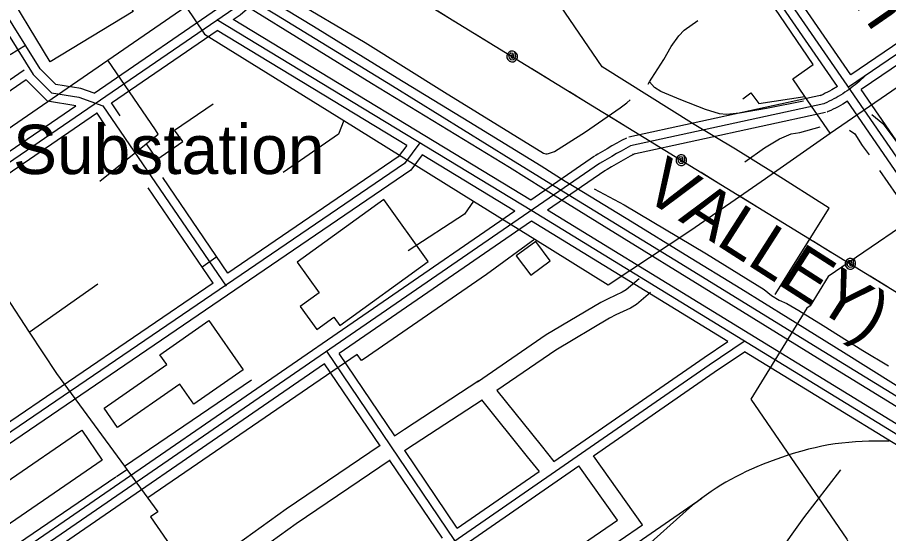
# Model space of a CAD drawing. Extents: x 3355724 to 3393621, y 594744 to 620174.
# Drawn here: x 3388659 to 3390126, y 612756 to 613624 of the extents above; entities that cross this region are included whole.
import ezdxf

# ---------------------------------------------------------------- set-up
doc = ezdxf.new("R2010")
doc.units = 0
for name, color, linetype in [('V-BLDG-OTLN', 7, 'Continuous'), ('V-RAIL-IDEN', 7, 'Continuous'), ('V-RAIL-TRAK', 7, 'Continuous'), ('V-ROAD-CNTR', 7, 'Continuous'), ('V-SITE-OTLN', 7, 'Continuous'), ('V-SITE-OTLN-IDEN', 7, 'Continuous'), ('V-TOPO-SHOR', 7, 'Continuous'), ('V-UTIL-LINE', 7, 'Continuous')]:
    doc.layers.add(name, color=color, linetype=linetype)

msp = doc.modelspace()

# ---------------------------------------------------------------- linework, layer by layer
at = {"layer": 'V-BLDG-OTLN'}
for points in [[(3389276.3, 613317.6), (3389130.3, 613212.5), (3389167.5, 613160.8), (3389135.6, 613137.8), (3389163.5, 613099), (3389192.3, 613119.7), (3389202.1, 613106), (3389351.3, 613213.3)], [(3389499.5, 613223.1), (3389523.8, 613190.3), (3389556.5, 613214.5), (3389532.3, 613247.3)], [(3388805.5, 612966.6), (3388910.8, 613039.9), (3388899.2, 613056.6), (3388982, 613114.2), (3389039.7, 613031.1), (3388956.3, 612973.1), (3388932.8, 613006.9), (3388828.1, 612934.1)], [(3388802, 612879.2), (3388593.4, 612736.1), (3388553.1, 612794.8), (3388634.4, 612850.6), (3388640.2, 612842), (3388767.7, 612929.4)]]:
    msp.add_lwpolyline(points, close=True, dxfattribs=at)
at = {"layer": 'V-RAIL-TRAK'}
for points in [[(3386835.4, 615018.6), (3387087.4, 614863.9), (3387313.5, 614724.5), (3387544.4, 614583), (3387825.6, 614410.3), (3388103.4, 614239), (3388374.3, 614072.6), (3388614, 613924.9), (3388857.9, 613775.8), (3389039.2, 613663.6), (3389053.7, 613654.6), (3389095.5, 613628.7), (3389291.1, 613509.4), (3389490.1, 613386), (3389587.1, 613326.5), (3389784.2, 613205.7), (3390000.1, 613072.5), (3390330.9, 612870), (3390414.6, 612817.9), (3390427.8, 612809.7), (3390622.7, 612689.7), (3390866.5, 612539.9), (3391139.5, 612371.4), (3391416.1, 612201.7)], [(3390974.6, 612456.2), (3390930.5, 612483.4), (3390784.4, 612573.4), (3390580, 612698.3), (3390429.2, 612790.4), (3390418.4, 612797), (3390349.8, 612839.6), (3390252.6, 612899.9), (3390033.2, 613034.5), (3389842.4, 613152.4), (3389647.5, 613272.3), (3389573.9, 613318.1), (3389487.9, 613371.5), (3389255.7, 613513), (3389041.3, 613645.3), (3389025.5, 613655.1), (3389018.6, 613659.3), (3388791.8, 613798.7), (3388745.6, 613827.1), (3388519.5, 613965.9)], [(3390176.9, 612981.4), (3390050.6, 613060.4), (3389957.5, 613118), (3389877.4, 613167.2), (3389783.7, 613224.8), (3389694.7, 613279.6), (3389599.6, 613337.6), (3389596.9, 613339.2), (3389582, 613348.3), (3389541.2, 613373.9), (3389419.7, 613448.8), (3389298.8, 613522.3), (3389158.2, 613609), (3389067.1, 613664.5)], [(3390127.6, 612911.2), (3390116.2, 612911.3), (3390104.8, 612911.2), (3390093.4, 612910.9), (3390082, 612910.5), (3390070.7, 612909.8), (3390059.3, 612908.9), (3390048, 612907.8), (3390036.6, 612906.5), (3390025.3, 612905), (3390014.1, 612902.7), (3390002.9, 612900.1), (3389991.7, 612897.4), (3389980.6, 612894.4), (3389969.5, 612891.2), (3389958.5, 612887.8), (3389947.6, 612884.2), (3389936.7, 612880.4), (3389925.9, 612876.4), (3389915.2, 612872.2), (3389904.6, 612867.9), (3389895.6, 612864), (3389886.8, 612859.9), (3389878.1, 612855.7), (3389869.4, 612851.3), (3389860.9, 612846.6), (3389852.4, 612841.8), (3389844.1, 612836.8), (3389835.9, 612831.7), (3389827.7, 612826.3), (3389819.8, 612820.8), (3389811.9, 612815.1), (3389804.1, 612809.2), (3389796.5, 612803.2), (3389704.7, 612721.2)], [(3389488, 612592.6), (3389696, 612735), (3389811.9, 612815.1)]]:
    msp.add_lwpolyline(points, dxfattribs=at)
at = {"layer": 'V-ROAD-CNTR'}
for p, q in [((3388647.3, 613561.9), (3388672.8, 613577.8)), ((3388970.4, 613204.7), (3388995.2, 613221.7))]:
    msp.add_line(p, q, dxfattribs=at)
for points in [[(3390234.3, 613253.1), (3389505.6, 614309.5)], [(3390063.1, 613527.6), (3389526.4, 614305.7)], [(3390040.3, 613507.8), (3389501.8, 614288.5)], [(3390888.5, 614071.8), (3390059.2, 613506.8)], [(3388788.5, 613496.8), (3388766.4, 613504.7), (3388724.2, 613511.5), (3388697.9, 613537.6), (3388421.7, 613980.6), (3388367, 614026.6), (3388297.2, 614032), (3388238.6, 614002.7), (3388164.4, 613952.2), (3387903.7, 613779), (3387846.4, 613745.2), (3387793.4, 613730.2), (3387568.5, 613587.9), (3387066.4, 613241.4)], [(3387074.8, 613229), (3387576.8, 613575.4), (3387799.6, 613716.3), (3387852.4, 613731.3), (3387911.7, 613766.3), (3388172.8, 613939.8), (3388246.2, 613989.8), (3388300.2, 614016.8), (3388361, 614012), (3388410.2, 613970.7), (3388686.1, 613528.2), (3388717.1, 613497.4), (3388762.7, 613490.1), (3388803.1, 613475.6), (3389011, 613171.9)], [(3388788.5, 613496.8), (3389016.1, 613652.6), (3389116.7, 613739.6)], [(3384630.6, 610636), (3387016, 612269.2), (3387921, 612884.9), (3389025.3, 613640.7), (3389125.7, 613727.5)], [(3389023, 613620.9), (3389034.5, 613628.8), (3389135.5, 613716.2)], [(3390301.7, 613690.2), (3390063.1, 613527.6)], [(3390318.7, 613665.4), (3390080.2, 613502.9)], [(3390435.6, 612759.5), (3390399.6, 612766.7), (3390358, 612788.6), (3389525.7, 613298.5), (3388995.4, 613620.2)], [(3389524.2, 613317), (3389023, 613620.9)], [(3388817.9, 613480.5), (3388995.9, 613602.3)], [(3389315.1, 613408.7), (3388995.9, 613602.3)], [(3388670.9, 613535.3), (3385357.8, 611252.6), (3385313, 611226.2), (3385260.2, 611196), (3385117.8, 611111.2), (3384941.1, 610983.2), (3384675.1, 610796)], [(3388673.9, 613519.1), (3387797, 612915)], [(3388757.7, 613475.7), (3388709.9, 613483.4), (3388673.9, 613519.1)], [(3390086.7, 613525.5), (3390083.5, 613522.5), (3390080.3, 613519.6), (3390077.1, 613516.7), (3390073.7, 613513.9), (3390070.4, 613511.1), (3390067, 613508.4), (3390063.5, 613505.8), (3390060, 613503.2), (3390056.5, 613500.7), (3390052.9, 613498.3), (3390049.2, 613495.9), (3390045.5, 613493.6), (3390041.8, 613491.4), (3390038, 613489.2), (3390034.2, 613487.1), (3390030.4, 613485.1), (3390026.5, 613483.1), (3390022.6, 613481.2), (3390018.6, 613479.4), (3390017.2, 613478.8)], [(3390040.3, 613507.8), (3390030.7, 613502.3), (3390027.1, 613500.3), (3390023.5, 613498.4), (3390019.9, 613496.6), (3390016.2, 613494.8), (3390012.5, 613493.1), (3390011.1, 613492.5)], [(3390246.6, 613261.6), (3390080.2, 613502.9)], [(3390014, 613493.4), (3389688.8, 613422.7)], [(3387842, 612849.3), (3387912.5, 612897.3), (3388757.7, 613475.7)], [(3388832.7, 613458.9), (3388817.9, 613480.5)], [(3390017.2, 613478.8), (3389692, 613408.1)], [(3390057.3, 613483.2), (3390049.4, 613478.4), (3390045.4, 613476.1), (3390041.3, 613473.9), (3390037.3, 613471.8), (3390033.1, 613469.7), (3390029, 613467.7), (3390024.8, 613465.8), (3390023.3, 613465.1)], [(3390221.9, 613244.6), (3390057.3, 613483.2)], [(3388423, 613210.3), (3388792.8, 613463.4)], [(3388808, 613441.9), (3388793.5, 613463.1), (3388792.8, 613463.4)], [(3390020.4, 613464.1), (3389695.2, 613393.4)], [(3389337, 613413), (3389311.3, 613378.5), (3388050.2, 612519.4)], [(3389684.9, 613421.3), (3389676.8, 613416.9), (3389668.7, 613412.5), (3389660.7, 613408), (3389652.7, 613403.4), (3389644.8, 613398.8), (3389636.9, 613394.1), (3389632.1, 613391.2)], [(3389315.1, 613408.7), (3389300.8, 613389.5), (3389014, 613194.1)], [(3389692, 613408.1), (3389684, 613403.8), (3389676, 613399.4), (3389668.1, 613395), (3389660.2, 613390.4), (3389652.4, 613385.9), (3389644.6, 613381.2), (3389639.9, 613378.3)], [(3389340.9, 613393.1), (3389321.8, 613367.5), (3388518.4, 612820.2)], [(3389497.1, 613298.3), (3389340.9, 613393.1)], [(3389631.4, 613390.7), (3389524.2, 613317)], [(3389699.1, 613394.9), (3389691.2, 613390.6), (3389683.3, 613386.3), (3389675.5, 613381.9), (3389667.7, 613377.5), (3389660, 613372.9), (3389652.3, 613368.3), (3389647.7, 613365.5)], [(3389639.9, 613378.3), (3388159.3, 612360.2)], [(3389014, 613194.1), (3388904.1, 613354.7)], [(3389648.4, 613366), (3389552.2, 613299.9)], [(3388989.2, 613177.2), (3388879.4, 613337.6)], [(3389497.1, 613298.3), (3388609.4, 612687.9)], [(3390438.6, 612774.2), (3390404.7, 612781), (3390365.5, 612801.7), (3389552.2, 613299.9)], [(3389525.2, 613281.3), (3389201.3, 613058.5)], [(3389855.8, 613078.7), (3389525.2, 613281.3)], [(3388989.2, 613177.2), (3388501.4, 612844.9)], [(3389706.5, 613184.1), (3389684.6, 613165.8), (3389677.7, 613161.6), (3389654.1, 613150.7), (3389642.1, 613144.5), (3389549.8, 613089.8), (3389434.1, 613010.6)], [(3389725.7, 613161.1), (3389702.1, 613141.3), (3389691.7, 613135), (3389667.3, 613123.8), (3389656.6, 613118.2), (3389565.9, 613064.4), (3389466.7, 612996.6), (3389541.3, 612903.5), (3389562.7, 612877)], [(3388378.7, 612040.5), (3389824.6, 613039.7), (3389883.5, 613079.3)], [(3389562.8, 612877.1), (3389816.1, 613052.1), (3389855.8, 613078.7)], [(3389396.1, 612743.6), (3389180.5, 613062.5)], [(3389295, 612919.9), (3389201.3, 613058.5)], [(3389629.3, 612886.5), (3389833, 613027.3), (3389883.9, 613061.5)], [(3390281.9, 612817.7), (3389883.9, 613061.5)], [(3389176.6, 613041.5), (3388626.4, 612663.2)], [(3389270.2, 612903.1), (3389176.6, 613041.5)], [(3389436.7, 613012.4), (3389311.1, 612930.5), (3389294.6, 612919.6)], [(3389442.1, 612980.1), (3389327.5, 612905.4), (3389311.2, 612894.6)], [(3389441, 612980.7), (3389517.9, 612884.7), (3389537.9, 612859.9)], [(3389270.5, 612903.6), (3389112, 612796.7), (3388915.4, 612655), (3388722.3, 612523.4)], [(3389400.1, 612764.6), (3389311.7, 612895.2)], [(3389428.3, 612580.9), (3389599, 612692.9), (3389712.3, 612770.5), (3389629.5, 612886.6)], [(3389287.4, 612878.8), (3389129.1, 612772), (3388932.6, 612630.5), (3388739.4, 612498.8)], [(3389375.4, 612747.5), (3389286.7, 612878.7)], [(3389347.7, 612691.9), (3389604.7, 612869.6)], [(3389411.2, 612605.6), (3389582.3, 612717.8), (3389670.1, 612777.9), (3389604.8, 612869.6)], [(3389400.1, 612764.6), (3389538.3, 612860.1)]]:
    msp.add_lwpolyline(points, dxfattribs=at)
at = {"layer": 'V-SITE-OTLN'}
msp.add_lwpolyline([(3388630.7, 613687.9), (3388770.4, 613772.7), (3388854.3, 613634.4), (3388714.6, 613549.6)], close=True, dxfattribs=at)
at = {"layer": 'V-TOPO-SHOR'}
for points in [[(3389115.6, 613659.1), (3389244.8, 613582), (3389378.7, 613498.7), (3389545.3, 613396), (3389549.4, 613394.6), (3389551.4, 613394.6), (3389553.5, 613395.2), (3389563.8, 613398.5), (3389616, 613431.6), (3389674.5, 613472), (3389685.5, 613480.8), (3389691.1, 613485.6)], [(3389721.4, 613511.9), (3389723.8, 613515.9), (3389727.6, 613522.1), (3389747.8, 613553.4), (3389760.3, 613575.2), (3389773.4, 613593.5), (3389782.4, 613603), (3389805.1, 613619.2)], [(3389983, 613483.5), (3389920.7, 613471.1), (3389875.5, 613463.3), (3389853.6, 613460.8), (3389842, 613462.3), (3389818.1, 613469.3), (3389776.5, 613485.4), (3389743.2, 613499.4), (3389732.3, 613506.4), (3389723.8, 613515.9)], [(3390098, 613460.7), (3390117, 613445.6), (3390135.8, 613420.8), (3390189, 613344), (3390241.5, 613271.9), (3390264.4, 613241)], [(3389884.2, 613381.2), (3389917.8, 613404.8), (3389942.5, 613420.2), (3389962.3, 613428.2), (3389977.3, 613430.8), (3390011.5, 613440)], [(3390060.6, 613434.8), (3390069.4, 613428.6), (3390082.1, 613408.7), (3390093.6, 613392.9)], [(3390111.1, 613366.8), (3390139.3, 613326.3), (3390187.8, 613256.3), (3390217.4, 613214.5)], [(3389630.9, 613335.7), (3389681.2, 613308.6), (3389819.9, 613226.6), (3389917.1, 613166.2), (3389929.4, 613156.5), (3389942.3, 613148.2), (3389955.2, 613142.6), (3389975.6, 613130.8), (3390016.4, 613105.8), (3390083, 613063.5), (3390126.5, 613037.7)], [(3389937.5, 612717.7), (3389983.8, 612782), (3390045.9, 612862.6)]]:
    msp.add_lwpolyline(points, dxfattribs=at)
at = {"layer": 'V-UTIL-LINE'}
for p, q in [((3390027.9, 613429.7), (3390255.4, 613585.2)), ((3389868.7, 613402.4), (3389799.2, 613444.2)), ((3389793.4, 613266.1), (3389919, 613353.3)), ((3388679.1, 613094.6), (3388794.8, 613175.9)), ((3388839.5, 612869.1), (3389053.7, 613014.2)), ((3388826.3, 612851.8), (3388843.6, 612863.5))]:
    msp.add_line(p, q, dxfattribs=at)
for points in [[(3390862.5, 618393.4), (3386415.7, 615396.7), (3387373.6, 614856.8), (3390174.5, 613140.8)], [(3389799.2, 613444.2), (3389643.9, 613540.9), (3389373.3, 613938.3), (3389272.1, 614082.5), (3389259.3, 614100.8)], [(3389511.5, 614033.3), (3389373.3, 613938.3), (3388943.3, 613642.6), (3388974.4, 613596.4), (3389209.1, 613450.7), (3389427.7, 613314.9), (3389530.9, 613250.8), (3389654.2, 613174.2), (3389793.4, 613266.1)], [(3389965, 613520.7), (3389999.5, 613545.1), (3389925.2, 613654.7)], [(3388500.1, 613337.7), (3388512.2, 613348.9), (3388562.9, 613381.6), (3388565.6, 613383.6), (3388811.8, 613552.4), (3388943.3, 613642.6)], [(3389367.2, 613635.3), (3389396.2, 613617.6)], [(3389430.3, 613596.7), (3389459.3, 613578.9)], [(3389492.6, 613558.5), (3389492.4, 613561.4), (3389490.6, 613560), (3389490.8, 613557.2), (3389493.4, 613556), (3389495.4, 613558.8), (3389494.4, 613563.4), (3389490.1, 613563.9), (3389486.6, 613560.6), (3389487.4, 613556.1), (3389490.6, 613553), (3389495.4, 613553.6), (3389498.6, 613558.2), (3389497.3, 613566.2), (3389494, 613567.4), (3389490.5, 613567.3), (3389487.3, 613565.8), (3389484.9, 613563.2), (3389483.7, 613559.9), (3389483.8, 613556.4), (3389485.3, 613553.3), (3389487.9, 613550.9), (3389491.2, 613549.7), (3389494.7, 613549.8), (3389497.9, 613551.3), (3389500.2, 613553.8), (3389501.5, 613557.1), (3389501.3, 613560.6), (3389499.8, 613563.8), (3389497.3, 613566.2)], [(3388798.4, 613348.5), (3388876.4, 613411.5), (3388896.7, 613427.9), (3388892.2, 613435.3), (3388811.8, 613552.4)], [(3389525.8, 613538.2), (3389554.8, 613520.4)], [(3389919, 613353.3), (3389932.4, 613362.7), (3390027.9, 613429.7), (3389985.4, 613491.3), (3389965, 613520.7)], [(3389588.9, 613499.5), (3389617.9, 613481.8)], [(3389880.9, 613487.1), (3389894.6, 613497.2), (3389908.1, 613479.3), (3389985.4, 613491.3)], [(3388876.4, 613411.5), (3388894.4, 613385.4), (3388937.8, 613415.6), (3388924, 613434.3), (3388988.9, 613478.9)], [(3389652, 613460.9), (3389681, 613443.1)], [(3389209.1, 613450.7), (3389200.2, 613427.8), (3389106.7, 613363.5)], [(3389715.1, 613422.2), (3389744.1, 613404.4)], [(3389935.6, 613157.9), (3390026.7, 613303), (3389932.4, 613362.7), (3389868.7, 613402.4)], [(3389777.4, 613384.1), (3389777.2, 613386.9), (3389775.4, 613385.5), (3389775.6, 613382.8), (3389778.2, 613381.5), (3389780.2, 613384.3), (3389779.2, 613388.9), (3389774.9, 613389.4), (3389771.4, 613386.1), (3389772.2, 613381.6), (3389775.4, 613378.5), (3389780.2, 613379.2), (3389783.4, 613383.7), (3389782.1, 613391.7), (3389778.8, 613392.9), (3389775.3, 613392.8), (3389772.1, 613391.3), (3389769.7, 613388.8), (3389768.5, 613385.5), (3389768.6, 613382), (3389770.1, 613378.8), (3389772.7, 613376.4), (3389776, 613375.2), (3389779.5, 613375.3), (3389782.6, 613376.8), (3389785, 613379.4), (3389786.2, 613382.6), (3389786.1, 613386.2), (3389784.6, 613389.3), (3389782.1, 613391.7)], [(3389810.6, 613363.7), (3389839.6, 613345.9)], [(3388512.2, 613348.9), (3388601.2, 613213.3), (3388679.1, 613094.6), (3388725, 613024.8), (3388839.5, 612869.1), (3388843.6, 612863.5), (3388896.1, 612792.1), (3388883.4, 612783.6), (3388927.3, 612720.1)], [(3389873.7, 613325), (3389902.7, 613307.3)], [(3389427.7, 613314.9), (3389412.2, 613293.1), (3389317.4, 613231.6)], [(3390217, 613319.5), (3390024.8, 613188.3), (3389994.3, 613138.8), (3389988.8, 613134.7), (3389894.6, 612981.5), (3390056.1, 612746), (3390058.1, 612742.5), (3390056.7, 612739.8), (3389970.2, 612679.2), (3390068, 612538.3), (3390126.4, 612454)], [(3389936.8, 613286.4), (3389965.8, 613268.6)], [(3389530.9, 613250.8), (3389449.1, 613191.8), (3389241.9, 613048.3), (3389238.6, 613047), (3389231.4, 613057.1), (3388878.9, 612815.6)], [(3389999.9, 613247.7), (3390028.9, 613230)], [(3390062.2, 613209.6), (3390062, 613212.4), (3390060.2, 613211), (3390060.4, 613208.3), (3390063, 613207), (3390064.9, 613209.8), (3390064, 613214.4), (3390059.7, 613214.9), (3390056.2, 613211.6), (3390057, 613207.1), (3390060.2, 613204), (3390065, 613204.7), (3390068.2, 613209.2), (3390066.9, 613217.2), (3390063.6, 613218.5), (3390060.1, 613218.3), (3390056.9, 613216.8), (3390054.5, 613214.3), (3390053.3, 613211), (3390053.4, 613207.5), (3390054.9, 613204.3), (3390057.5, 613201.9), (3390060.7, 613200.7), (3390064.3, 613200.8), (3390067.4, 613202.3), (3390069.8, 613204.9), (3390071, 613208.2), (3390070.9, 613211.7), (3390069.4, 613214.9), (3390066.9, 613217.2)], [(3390095.4, 613189.2), (3390124.4, 613171.4)], [(3388373.9, 612543.3), (3388635.1, 612721.5), (3388825, 612851.2)]]:
    msp.add_lwpolyline(points, dxfattribs=at)

# ---------------------------------------------------------------- texts
at = {"layer": 'V-RAIL-IDEN'}
msp.add_text('VALLEY)', height=83, rotation=327.3626, dxfattribs=at).set_placement((3389708.8, 613323.1))
at = {"layer": 'V-SITE-OTLN-IDEN'}
msp.add_text('Substation', height=83, rotation=304.6533, dxfattribs=at).set_placement((3389802.8, 614030.2))
msp.add_text('Substation', height=83, dxfattribs=at).set_placement((3388652, 613360.7))

doc.saveas('drawing.dxf')
